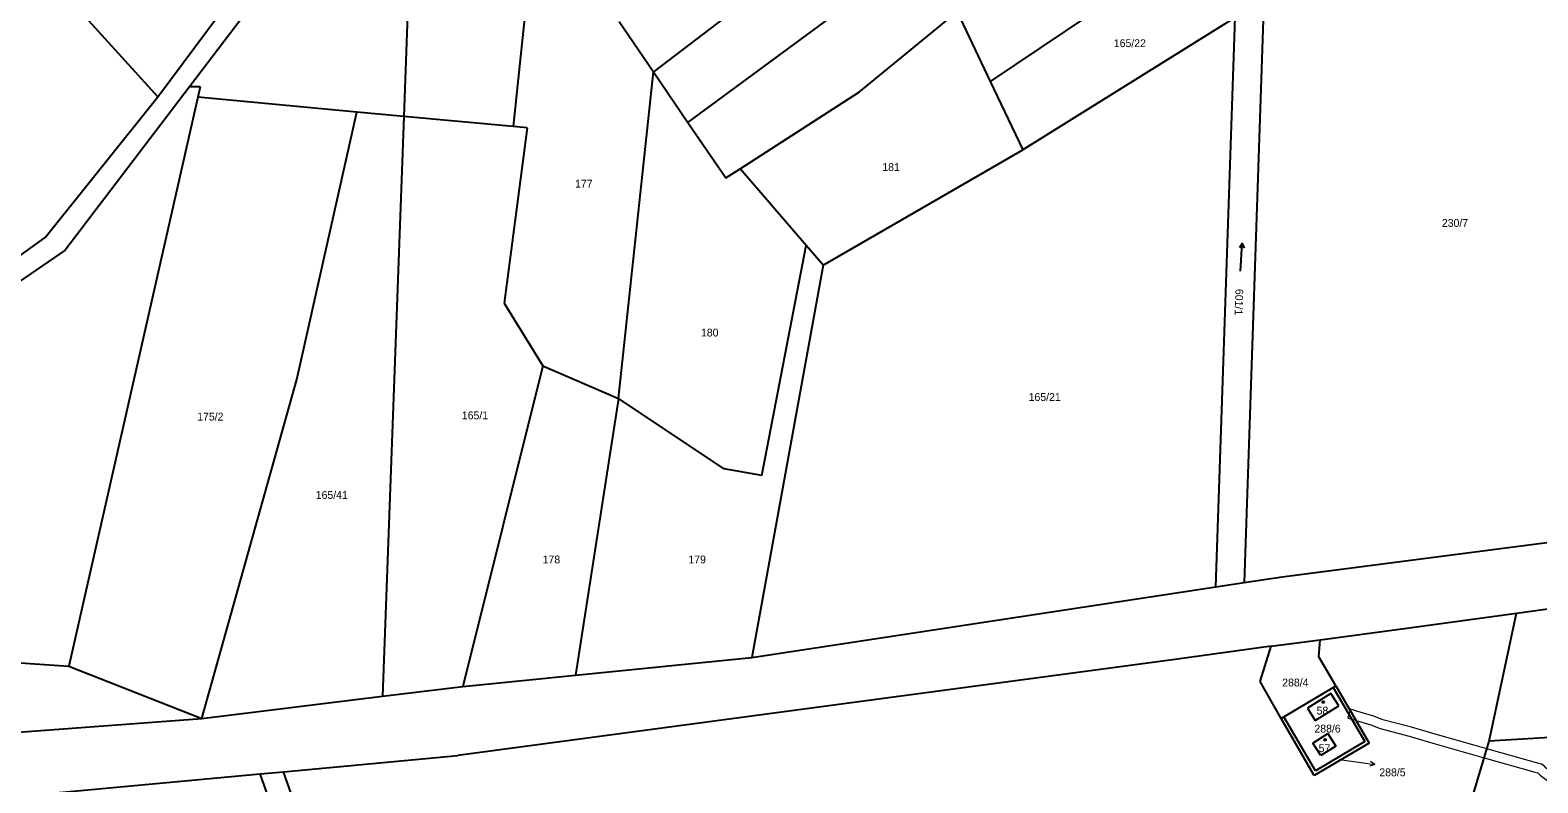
# Model space of a CAD drawing. Extents: x -664548 to -662415, y -1069720 to -1068208.
# Drawn here: x -663233.8 to -662907.1, y -1068901.8 to -1068738.8 of the extents above; entities that cross this region are included whole.
import ezdxf

# ---------------------------------------------------------------- set-up
doc = ezdxf.new("R2010")
doc.units = 0
doc.header["$LTSCALE"] = 0.68
for name, color, linetype, lineweight in [('1', 7, 'Continuous', 25), ('13', 7, 'Continuous', 13), ('3', 7, 'Continuous', 25), ('5', 7, 'Continuous', 25), ('7', 7, 'Continuous', 13)]:
    doc.layers.add(name, color=color, linetype=linetype, lineweight=lineweight)
doc.layers.add('2', color=7, linetype='Continuous')

msp = doc.modelspace()

# ---------------------------------------------------------------- linework, layer by layer
at = {"layer": '1'}
for p, q in [((-662969.8, -1068649.75), (-663098.77, -1068747.81)), ((-663091.29, -1068758.78), (-662970.49, -1068669.91)), ((-663206.12, -1068753.27), (-663149.89, -1068677.42)), ((-663152.9, -1068690.09), (-663199.29, -1068751.1)), ((-663150.39, -1068690.96), (-663152.83, -1068757.51)), ((-663123.64, -1068707.84), (-663129.18, -1068759.71)), ((-662966.49, -1068732.18), (-662970.79, -1068858.47)), ((-663223.3, -1068734.34), (-663206.12, -1068753.27)), ((-663054.1, -1068752.18), (-663032.93, -1068734.82)), ((-663032.93, -1068734.82), (-663025.78, -1068749.9)), ((-663106.19, -1068736.93), (-663098.77, -1068747.81)), ((-662972.74, -1068736.07), (-663018.75, -1068764.74)), ((-662976.93, -1068859.41), (-662972.74, -1068736.07)), ((-663106.34, -1068818.57), (-663098.77, -1068747.81)), ((-663098.77, -1068747.81), (-663091.29, -1068758.78)), ((-663199.29, -1068751.1), (-663226.21, -1068786.49)), ((-663196.99, -1068751.1), (-663199.29, -1068751.1)), ((-663196.99, -1068751.1), (-663197.5, -1068753.36)), ((-663025.78, -1068749.9), (-663018.75, -1068764.74)), ((-663230.57, -1068783.74), (-663206.12, -1068753.27)), ((-663197.5, -1068753.36), (-663225.45, -1068876.61)), ((-663163.02, -1068756.56), (-663197.5, -1068753.36)), ((-663079.98, -1068768.83), (-663054.1, -1068752.18)), ((-663176.03, -1068814.48), (-663163.02, -1068756.56)), ((-663152.83, -1068757.51), (-663163.02, -1068756.56)), ((-663152.83, -1068757.51), (-663157.43, -1068883.09)), ((-663129.18, -1068759.71), (-663152.83, -1068757.51)), ((-663126.08, -1068760), (-663131.11, -1068797.97)), ((-663126.08, -1068760), (-663129.18, -1068759.71)), ((-663091.29, -1068758.78), (-663083.07, -1068770.82)), ((-663061.95, -1068789.74), (-663018.75, -1068764.74)), ((-663083.07, -1068770.82), (-663079.98, -1068768.83)), ((-663065.66, -1068785.44), (-663079.98, -1068768.83)), ((-663258.34, -1068803.65), (-663230.57, -1068783.74)), ((-663226.21, -1068786.49), (-663259.22, -1068809.05)), ((-663075.24, -1068835.3), (-663065.66, -1068785.44)), ((-663061.95, -1068789.74), (-663065.66, -1068785.44)), ((-663061.95, -1068789.74), (-663077.44, -1068874.73)), ((-663131.11, -1068797.97), (-663122.71, -1068811.55)), ((-663122.71, -1068811.55), (-663140.06, -1068880.96)), ((-663122.71, -1068811.55), (-663106.34, -1068818.57)), ((-663196.6, -1068887.88), (-663176.03, -1068814.48)), ((-663106.34, -1068818.57), (-663115.67, -1068878.53)), ((-663083.44, -1068833.8), (-663106.34, -1068818.57)), ((-663075.24, -1068835.3), (-663083.44, -1068833.8)), ((-662962.55, -1068857.22), (-662900.68, -1068849.24)), ((-662911.77, -1068865.09), (-662813.46, -1068851.51)), ((-663077.44, -1068874.73), (-662976.93, -1068859.41)), ((-662976.93, -1068859.41), (-662970.79, -1068858.47)), ((-662970.79, -1068858.47), (-662962.55, -1068857.22)), ((-662935.53, -1068868.37), (-662911.77, -1068865.09)), ((-662917.67, -1068892.82), (-662911.77, -1068865.09)), ((-662954.32, -1068870.88), (-662935.53, -1068868.37)), ((-662964.89, -1068872.21), (-662985.22, -1068875.03)), ((-662967.27, -1068879.87), (-662964.89, -1068872.21)), ((-662964.89, -1068872.21), (-662954.32, -1068870.88)), ((-662954.56, -1068874.55), (-662954.32, -1068870.88)), ((-663251.85, -1068874.7), (-663225.45, -1068876.61)), ((-662985.22, -1068875.03), (-663141.13, -1068895.92)), ((-663115.67, -1068878.53), (-663077.44, -1068874.73)), ((-662950.89, -1068880.81), (-662954.56, -1068874.55)), ((-663225.45, -1068876.61), (-663196.6, -1068887.88)), ((-663140.06, -1068880.96), (-663115.67, -1068878.53)), ((-663157.43, -1068883.09), (-663140.06, -1068880.96)), ((-662962.75, -1068887.92), (-662967.27, -1068879.87)), ((-662962.13, -1068887.53), (-662951.48, -1068881.17)), ((-662951.98, -1068882.47), (-662957.06, -1068885.66)), ((-662950.27, -1068885.19), (-662951.98, -1068882.47)), ((-662951.48, -1068881.17), (-662950.89, -1068880.81)), ((-662951.48, -1068881.17), (-662944.63, -1068892.93)), ((-662950.89, -1068880.81), (-662943.64, -1068893.27)), ((-663196.6, -1068887.88), (-663157.43, -1068883.09)), ((-662957.06, -1068885.66), (-662955.37, -1068888.38)), ((-662955.37, -1068888.38), (-662950.27, -1068885.19)), ((-663347.26, -1068899.14), (-663196.6, -1068887.88)), ((-662962.75, -1068887.92), (-662962.13, -1068887.53)), ((-662955.6, -1068900.29), (-662962.75, -1068887.92)), ((-662955.32, -1068899.22), (-662962.13, -1068887.53)), ((-662955.87, -1068893.25), (-662952.6, -1068891.19)), ((-662952.6, -1068891.19), (-662950.92, -1068893.92)), ((-662864.66, -1068889.63), (-662917.67, -1068892.82)), ((-662954.14, -1068895.96), (-662955.87, -1068893.25)), ((-662943.64, -1068893.27), (-662955.6, -1068900.29)), ((-662944.63, -1068892.93), (-662955.32, -1068899.22)), ((-662950.92, -1068893.92), (-662954.14, -1068895.96)), ((-662926.47, -1068922.26), (-662917.67, -1068892.82)), ((-663178.89, -1068899.43), (-663141.13, -1068895.92)), ((-663227.49, -1068903.95), (-663183.95, -1068899.9)), ((-663183.95, -1068899.9), (-663178.89, -1068899.43)), ((-663180.11, -1068910.85), (-663183.95, -1068899.9)), ((-663176.02, -1068907.61), (-663178.89, -1068899.43))]:
    msp.add_line(p, q, dxfattribs=at)
msp.add_lwpolyline([(-662971.19, -1068690.4), (-662971.98, -1068713.76), (-663025.78, -1068749.9)], dxfattribs=at)
at = {"layer": '13'}
for points in [[(-662941.3, -1068890.09), (-662935.02, -1068891.74), (-662929.4, -1068893.39), (-662921.27, -1068895.7), (-662918.75, -1068896.42), (-662918.17, -1068894.51), (-662920.73, -1068893.78), (-662928.84, -1068891.47), (-662934.48, -1068889.82), (-662940.68, -1068888.19), (-662942.65, -1068887.39), (-662946.66, -1068886.22), (-662947.18, -1068886.07), (-662947.76, -1068885.91), (-662947.81, -1068886.1), (-662948.3, -1068887.83), (-662947.72, -1068887.99), (-662947.22, -1068888.14), (-662946.5, -1068888.35), (-662943.31, -1068889.29)], [(-662907.96, -1068899.47), (-662907.16, -1068899.69), (-662907.02, -1068899.77), (-662906.63, -1068900.17), (-662892.2, -1068910.96), (-662877.92, -1068921.76), (-662874.66, -1068921.73), (-662875.31, -1068921.23), (-662891, -1068909.36), (-662905.31, -1068898.65), (-662905.78, -1068898.19), (-662906.36, -1068897.83), (-662907.44, -1068897.55), (-662918.17, -1068894.51), (-662918.75, -1068896.42)]]:
    msp.add_lwpolyline(points, close=True, dxfattribs=at)
at = {"layer": '3'}
msp.add_line((-662971.204, -1068785.027), (-662970.754, -1068786.029), dxfattribs=at)
msp.add_lwpolyline([(-662971.518, -1068791.019), (-662971.204, -1068785.027), (-662971.755, -1068785.977)], dxfattribs=at)
at = {"layer": '5'}
for centre in [(-662953.6268, -1068884.3692), (-662953.2168, -1068892.5192)]:
    msp.add_circle(centre, 0.175, dxfattribs=at)
at = {"layer": '7'}
msp.add_line((-662942.468, -1068897.878), (-662943.39, -1068897.242), dxfattribs=at)
msp.add_lwpolyline([(-662950.2, -1068896.83), (-662945.44, -1068897.46), (-662942.468, -1068897.878), (-662943.53, -1068898.234)], dxfattribs=at)

# ---------------------------------------------------------------- texts
at = {"layer": '2'}
for s, p in [('165/22', (-662999, -1068742.485)), ('181', (-663049.16, -1068769.314)), ('177', (-663115.74, -1068772.925)), ('230/7', (-662927.92, -1068781.415)), ('180', (-663088.45, -1068805.165)), ('165/21', (-663017.45, -1068819.125)), ('175/2', (-663197.61, -1068823.365)), ('165/1', (-663140.27, -1068823.104)), ('165/41', (-663171.92, -1068840.344)), ('178', (-663122.76, -1068854.314)), ('179', (-663091.18, -1068854.314)), ('288/4', (-662962.51, -1068880.965)), ('58', (-662955.06, -1068887.054)), ('288/6', (-662955.53, -1068890.955)), ('57', (-662954.62, -1068895.205)), ('288/5', (-662941.47, -1068900.425))]:
    msp.add_text(s, height=1.7, dxfattribs=at).set_placement(p)
msp.add_text('601/1', height=1.7, rotation=268, dxfattribs=at).set_placement((-662972.624, -1068794.835))

doc.saveas('drawing.dxf')
